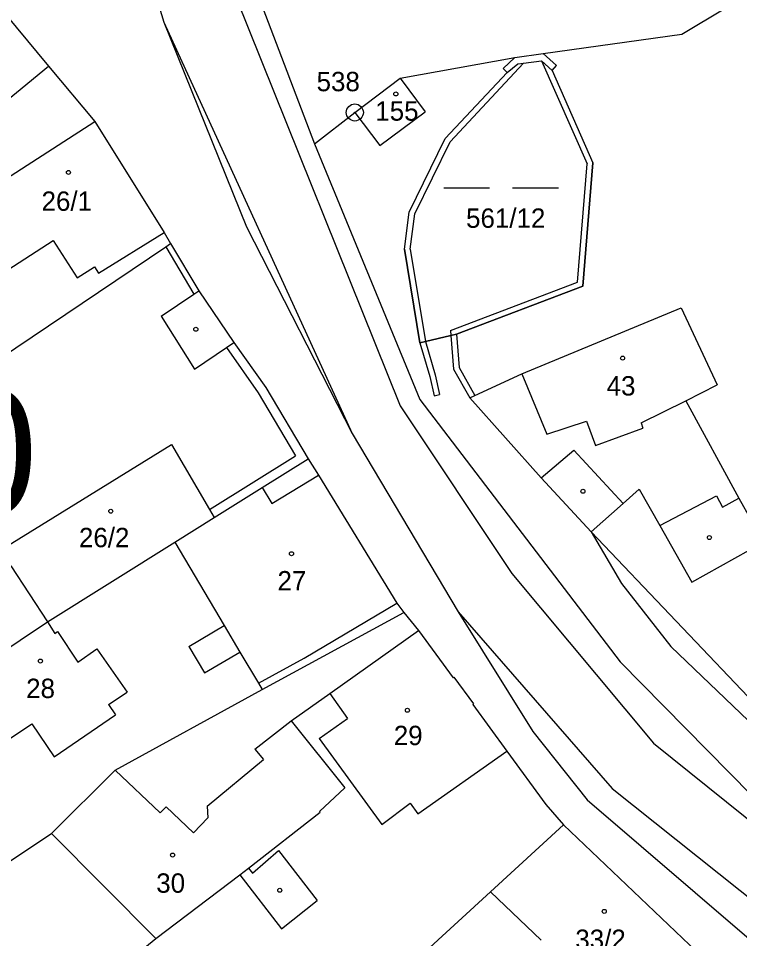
# Model space of a CAD drawing. Extents: x -725765 to -723182, y -1052705 to -1049154.
# Drawn here: x -724819.8 to -724756.6, y -1050950.1 to -1050869.4 of the extents above; entities that cross this region are included whole.
import ezdxf

# ---------------------------------------------------------------- set-up
doc = ezdxf.new("R2010")
doc.units = 0
for name, color, linetype in [('Vrstva 1', 7, 'Continuous'), ('Vrstva 17', 7, 'Continuous'), ('Vrstva 18', 7, 'Continuous'), ('Vrstva 19', 7, 'Continuous'), ('Vrstva 25', 7, 'Continuous'), ('Vrstva 4', 7, 'Continuous'), ('Vrstva 52', 7, 'Continuous'), ('Vrstva 53', 7, 'Continuous')]:
    doc.layers.add(name, color=color, linetype=linetype)

msp = doc.modelspace()

# ---------------------------------------------------------------- linework, layer by layer
at = {"layer": 'Vrstva 1'}
for points in [[(-724815.27, -1050842.75), (-724807.1, -1050869.67)], [(-724832.11, -1050855.56), (-724817.19, -1050873.53)], [(-724802.7, -1050857.13), (-724793.87, -1050880.36)], [(-724807.1, -1050869.67), (-724799.84, -1050887.62)], [(-724776.99, -1050874.1), (-724776.04, -1050873.34)], [(-724776.04, -1050873.34), (-724775.53, -1050873.27)], [(-724775.53, -1050873.27), (-724773.96, -1050873.06)], [(-724773.96, -1050873.06), (-724773.02, -1050873.91)], [(-724817.19, -1050873.53), (-724813.15, -1050878.39)], [(-724782.4, -1050879.89), (-724776.99, -1050874.1)], [(-724773.02, -1050873.91), (-724769.45, -1050882.02)], [(-724790.34, -1050877.6), (-724786.35, -1050874.6)], [(-724786.35, -1050874.6), (-724784.18, -1050877.55)], [(-724790.34, -1050877.6), (-724788.13, -1050880.5)], [(-724788.13, -1050880.5), (-724784.18, -1050877.55)], [(-724826.02, -1050886.69), (-724813.15, -1050878.39)], [(-724813.15, -1050878.39), (-724807.07, -1050888.13)], [(-724785.56, -1050886.34), (-724782.4, -1050879.89)], [(-724793.87, -1050880.36), (-724784.64, -1050902.78)], [(-724770.35, -1050892.84), (-724769.45, -1050882.02)], [(-724785.99, -1050889.59), (-724785.56, -1050886.34)], [(-724799.84, -1050887.62), (-724790.58, -1050905.75)], [(-724807.07, -1050888.13), (-724806.49, -1050889.1)], [(-724845.06, -1050915.06), (-724806.9, -1050889.38)], [(-724806.9, -1050889.38), (-724806.49, -1050889.1)], [(-724806.49, -1050889.1), (-724804.03, -1050893.25)], [(-724785.99, -1050889.59), (-724784.64, -1050897.81)], [(-724781.43, -1050897.06), (-724770.35, -1050892.84)], [(-724804.03, -1050893.25), (-724800.94, -1050897.77)], [(-724775.69, -1050900.52), (-724761.71, -1050894.73)], [(-724761.71, -1050894.73), (-724758.56, -1050901.48)], [(-724784.64, -1050897.81), (-724784.15, -1050897.7)], [(-724784.15, -1050897.7), (-724781.92, -1050897.18)], [(-724781.92, -1050897.18), (-724781.43, -1050897.06)], [(-724800.94, -1050897.77), (-724798.15, -1050901.74)], [(-724779.8, -1050902.43), (-724775.69, -1050900.52)], [(-724798.15, -1050901.74), (-724794.44, -1050907.99)], [(-724761.31, -1050902.89), (-724758.56, -1050901.48)], [(-724780.25, -1050902.64), (-724779.8, -1050902.43)], [(-724784.64, -1050902.78), (-724767.07, -1050925.79)], [(-724780.25, -1050902.64), (-724773.99, -1050909.66)], [(-724761.31, -1050902.89), (-724756.65, -1050911.44)], [(-724790.58, -1050905.75), (-724781.27, -1050921.4)], [(-724798.46, -1050910.5), (-724794.44, -1050907.99)], [(-724794.44, -1050907.99), (-724793.53, -1050909.41)], [(-724793.53, -1050909.41), (-724786.64, -1050920.65)], [(-724773.99, -1050909.66), (-724769.61, -1050914.39)], [(-724802.67, -1050913.13), (-724798.46, -1050910.5)], [(-724766.81, -1050911.91), (-724765.4, -1050910.66)], [(-724765.4, -1050910.66), (-724763.59, -1050913.84)], [(-724769.61, -1050914.39), (-724766.81, -1050911.91)], [(-724756.65, -1050911.44), (-724754.49, -1050915.3)], [(-724806.13, -1050915.3), (-724802.67, -1050913.13)], [(-724763.59, -1050913.84), (-724760.77, -1050918.8)], [(-724769.61, -1050914.39), (-724754.7, -1050930.05)], [(-724817.3, -1050922.28), (-724806.13, -1050915.3)], [(-724806.13, -1050915.3), (-724801.79, -1050922.61)], [(-724760.77, -1050918.8), (-724754.49, -1050915.3)], [(-724786.64, -1050920.65), (-724786.04, -1050921.45)], [(-724798.45, -1050928.23), (-724786.04, -1050921.45)], [(-724786.04, -1050921.45), (-724784.74, -1050923.04)], [(-724781.27, -1050921.4), (-724774.72, -1050931.91)], [(-724824.41, -1050927.04), (-724817.3, -1050922.28)], [(-724804.89, -1050924.45), (-724801.79, -1050922.61)], [(-724792.53, -1050928.57), (-724784.74, -1050923.04)], [(-724784.74, -1050923.04), (-724781.72, -1050927.21)], [(-724804.89, -1050924.45), (-724803.51, -1050926.77)], [(-724803.51, -1050926.77), (-724800.41, -1050924.93)], [(-724800.41, -1050924.93), (-724798.79, -1050927.66)], [(-724767.07, -1050925.79), (-724749.83, -1050943.31)], [(-724781.72, -1050927.21), (-724781.64, -1050927.15)], [(-724781.64, -1050927.15), (-724779.92, -1050929.48)], [(-724811.36, -1050935.29), (-724798.45, -1050928.23)], [(-724798.79, -1050927.66), (-724798.45, -1050928.23)], [(-724795.93, -1050930.98), (-724792.53, -1050928.57)], [(-724780, -1050929.54), (-724779.92, -1050929.48)], [(-724780, -1050929.54), (-724777.02, -1050933.62)], [(-724795.93, -1050930.98), (-724791.2, -1050936.85)], [(-724774.72, -1050931.91), (-724769.97, -1050937.91)], [(-724777.02, -1050933.62), (-724773.59, -1050938.3)], [(-724816.95, -1050940.84), (-724811.36, -1050935.29)], [(-724793.44, -1050938.91), (-724791.2, -1050936.85)], [(-724769.97, -1050937.91), (-724755.76, -1050950.09)], [(-724773.59, -1050938.3), (-724772.04, -1050940.08)], [(-724799.66, -1050943.89), (-724793.38, -1050938.99)], [(-724793.44, -1050938.91), (-724793.38, -1050938.99)], [(-724778.45, -1050945.98), (-724772.04, -1050940.08)], [(-724772.04, -1050940.08), (-724758.54, -1050952.96)], [(-724821.51, -1050943.86), (-724816.95, -1050940.84)], [(-724816.95, -1050940.84), (-724807.78, -1050950.05)], [(-724807.78, -1050950.05), (-724800.42, -1050944.47)], [(-724800.42, -1050944.47), (-724799.66, -1050943.89)], [(-724784.45, -1050951.5), (-724778.45, -1050945.98)], [(-724812.01, -1050953.52), (-724807.78, -1050950.05)]]:
    msp.add_lwpolyline(points, dxfattribs=at)
at = {"layer": 'Vrstva 25'}
for points in [[(-724782.535, -1050884.22), (-724778.515, -1050884.22)], [(-724776.504, -1050884.22), (-724772.484, -1050884.22)]]:
    msp.add_lwpolyline(points, dxfattribs=at)
for centre, radius in [((-724786.74, -1050875.98), 0.175), ((-724790.34, -1050877.6), 0.75), ((-724790.34, -1050877.6), 0.032), ((-724815.45, -1050882.86), 0.175), ((-724804.28, -1050896.62), 0.175), ((-724766.85, -1050899.15), 0.175), ((-724770.33, -1050910.83), 0.175), ((-724811.74, -1050912.58), 0.175), ((-724759.24, -1050914.89), 0.175), ((-724795.89, -1050916.31), 0.175), ((-724817.91, -1050925.72), 0.175), ((-724785.73, -1050930.04), 0.175), ((-724806.32, -1050942.74), 0.175), ((-724796.92, -1050945.83), 0.175), ((-724768.46, -1050947.68), 0.175)]:
    msp.add_circle(centre, radius, dxfattribs=at)
at = {"layer": 'Vrstva 4'}
for points in [[(-724761.65, -1050870.74), (-724750.38, -1050863.96)], [(-724800.77, -1050867.46), (-724786.35, -1050903.34)], [(-724807.1, -1050869.67), (-724790.58, -1050905.75)], [(-724773.82, -1050872.43), (-724761.65, -1050870.74)], [(-724776.31, -1050872.79), (-724773.82, -1050872.43)], [(-724773.82, -1050872.43), (-724772.64, -1050873.49)], [(-724786.35, -1050874.6), (-724776.31, -1050872.79)], [(-724781.98, -1050880.17), (-724775.53, -1050873.27)], [(-724777.32, -1050873.73), (-724776.31, -1050872.79)], [(-724773.96, -1050873.06), (-724769.96, -1050882.1)], [(-724773.02, -1050873.91), (-724772.64, -1050873.49)], [(-724826.16, -1050880.87), (-724817.19, -1050873.53)], [(-724777.32, -1050873.73), (-724776.99, -1050874.1)], [(-724793.87, -1050880.36), (-724790.34, -1050877.6)], [(-724785.07, -1050886.49), (-724781.98, -1050880.17)], [(-724770.82, -1050892.48), (-724769.96, -1050882.1)], [(-724785.48, -1050889.6), (-724785.07, -1050886.49)], [(-724812.82, -1050891.71), (-724807.07, -1050888.13)], [(-724822.3, -1050892.37), (-724816.8, -1050888.84)], [(-724816.8, -1050888.84), (-724814.7, -1050892.11)], [(-724806.9, -1050889.38), (-724804.45, -1050893.53)], [(-724785.48, -1050889.6), (-724784.15, -1050897.7)], [(-724814.7, -1050892.11), (-724813.18, -1050891.14)], [(-724813.18, -1050891.14), (-724812.82, -1050891.71)], [(-724781.96, -1050896.72), (-724770.82, -1050892.48)], [(-724807.33, -1050895.46), (-724804.45, -1050893.53)], [(-724804.45, -1050893.53), (-724804.03, -1050893.25)], [(-724807.33, -1050895.46), (-724804.39, -1050900.13)], [(-724781.96, -1050896.72), (-724781.92, -1050897.18)], [(-724784.15, -1050897.7), (-724783.28, -1050900.62)], [(-724781.92, -1050897.18), (-724781.68, -1050900.11)], [(-724781.43, -1050897.06), (-724781.19, -1050899.96)], [(-724804.39, -1050900.13), (-724801.6, -1050898.22)], [(-724801.6, -1050898.22), (-724800.94, -1050897.77)], [(-724801.6, -1050898.22), (-724798.81, -1050902.19)], [(-724784.64, -1050897.81), (-724783.76, -1050900.76)], [(-724781.68, -1050900.11), (-724780.25, -1050902.64)], [(-724781.19, -1050899.96), (-724779.8, -1050902.43)], [(-724783.76, -1050900.76), (-724783.39, -1050902.45)], [(-724783.28, -1050900.62), (-724782.9, -1050902.34)], [(-724775.69, -1050900.52), (-724773.49, -1050905.83)], [(-724798.81, -1050902.19), (-724795.53, -1050907.73)], [(-724783.39, -1050902.45), (-724782.9, -1050902.34)], [(-724786.35, -1050903.34), (-724776.58, -1050918.05)], [(-724765.23, -1050904.83), (-724761.31, -1050902.89)], [(-724773.49, -1050905.83), (-724770.01, -1050904.68)], [(-724770.01, -1050904.68), (-724769.22, -1050906.82)], [(-724765.23, -1050904.83), (-724765.09, -1050905.3)], [(-724769.22, -1050906.82), (-724765.09, -1050905.3)], [(-724821.4, -1050916), (-724806.41, -1050906.74)], [(-724806.41, -1050906.74), (-724803.07, -1050912.44)], [(-724773.99, -1050909.66), (-724771.12, -1050907.22)], [(-724771.12, -1050907.22), (-724766.81, -1050911.91)], [(-724803.07, -1050912.44), (-724795.53, -1050907.73)], [(-724797.61, -1050911.89), (-724793.53, -1050909.41)], [(-724798.46, -1050910.5), (-724797.61, -1050911.89)], [(-724763.59, -1050913.84), (-724758.63, -1050911.22)], [(-724758.63, -1050911.22), (-724758.09, -1050912.23)], [(-724758.09, -1050912.23), (-724756.65, -1050911.44)], [(-724803.07, -1050912.44), (-724802.67, -1050913.13)], [(-724769.61, -1050914.39), (-724766.96, -1050918.91)], [(-724820.51, -1050917.36), (-724817.3, -1050922.28)], [(-724776.58, -1050918.05), (-724764.15, -1050932.92)], [(-724766.96, -1050918.91), (-724762.62, -1050924.46)], [(-724794.79, -1050925.48), (-724786.64, -1050920.65)], [(-724781.27, -1050921.4), (-724767.77, -1050936.91)], [(-724817.3, -1050922.28), (-724816.64, -1050923.3)], [(-724801.79, -1050922.61), (-724800.41, -1050924.93)], [(-724816.64, -1050923.3), (-724816.4, -1050923.14)], [(-724816.4, -1050923.14), (-724814.62, -1050925.83)], [(-724814.62, -1050925.83), (-724812.95, -1050924.66)], [(-724812.95, -1050924.66), (-724810.29, -1050928.46)], [(-724762.62, -1050924.46), (-724755.82, -1050930.98)], [(-724798.79, -1050927.66), (-724794.79, -1050925.48)], [(-724811.95, -1050929.54), (-724810.29, -1050928.46)], [(-724792.53, -1050928.57), (-724790.97, -1050930.77)], [(-724811.95, -1050929.54), (-724811.33, -1050930.45)], [(-724816.69, -1050934.12), (-724811.33, -1050930.45)], [(-724793.46, -1050932.52), (-724790.97, -1050930.77)], [(-724822.44, -1050933.75), (-724818.66, -1050931.23)], [(-724818.66, -1050931.23), (-724816.69, -1050934.12)], [(-724799.11, -1050933.45), (-724795.93, -1050930.98)], [(-724793.46, -1050932.52), (-724787.96, -1050940.06)], [(-724764.15, -1050932.92), (-724737.04, -1050954.71)], [(-724799.11, -1050933.45), (-724798.35, -1050934.37)], [(-724784.82, -1050939.12), (-724777.02, -1050933.62)], [(-724803.28, -1050938.44), (-724798.35, -1050934.37)], [(-724811.36, -1050935.29), (-724807.41, -1050939.05)], [(-724767.77, -1050936.91), (-724739.7, -1050959.28)], [(-724807.41, -1050939.05), (-724806.88, -1050938.5)], [(-724806.88, -1050938.5), (-724804.47, -1050940.8)], [(-724803.28, -1050938.44), (-724803.22, -1050939.49)], [(-724787.96, -1050940.06), (-724785.47, -1050938.2)], [(-724785.47, -1050938.2), (-724784.82, -1050939.12)], [(-724804.47, -1050940.8), (-724803.22, -1050939.49)], [(-724799.31, -1050944.32), (-724797.03, -1050942.33)], [(-724797.03, -1050942.33), (-724793.64, -1050946.73)], [(-724800.42, -1050944.47), (-724796.78, -1050949.21)], [(-724799.66, -1050943.89), (-724799.31, -1050944.32)], [(-724778.45, -1050945.98), (-724774, -1050950.22)], [(-724796.78, -1050949.21), (-724793.64, -1050946.73)]]:
    msp.add_lwpolyline(points, dxfattribs=at)
at = {"layer": 'Vrstva 52'}
for points in [[(-724813.33, -1050644), (-724808.37, -1050650.73), (-724806.43, -1050654.63), (-724804.75, -1050661.51), (-724810.21, -1050691.79), (-724815, -1050731.09), (-724815.58, -1050758.85), (-724815.13, -1050787.45), (-724817.4, -1050803.09), (-724819.59, -1050825.69), (-724818.46, -1050833.53), (-724815.27, -1050842.75), (-724807.1, -1050869.67), (-724799.84, -1050887.62), (-724790.58, -1050905.75), (-724781.27, -1050921.4), (-724774.72, -1050931.91), (-724769.97, -1050937.91), (-724755.76, -1050950.09), (-724747.39, -1050955.27), (-724740.23, -1050960.06), (-724733.48, -1050964.31), (-724729, -1050967.94)], [(-724797.81, -1050648.79), (-724786.08, -1050660.92), (-724787.52, -1050665.42), (-724789.04, -1050670.2), (-724789.99, -1050673.16), (-724795.12, -1050673.64), (-724798.75, -1050677.64), (-724800.93, -1050691.71), (-724804.92, -1050728), (-724806.68, -1050763.03), (-724806.76, -1050807.12), (-724807.68, -1050827.87), (-724807.91, -1050834.06), (-724802.7, -1050857.13), (-724793.87, -1050880.36), (-724784.64, -1050902.78), (-724767.07, -1050925.79), (-724749.83, -1050943.31), (-724735.73, -1050952.08), (-724724.93, -1050961.09)], [(-724773.96, -1050873.06), (-724773.02, -1050873.91), (-724769.45, -1050882.02), (-724770.35, -1050892.84), (-724781.43, -1050897.06), (-724781.92, -1050897.18), (-724784.15, -1050897.7), (-724784.64, -1050897.81), (-724785.99, -1050889.59), (-724785.56, -1050886.34), (-724782.4, -1050879.89), (-724776.99, -1050874.1), (-724776.04, -1050873.34), (-724775.53, -1050873.27), (-724773.96, -1050873.06)]]:
    msp.add_lwpolyline(points, dxfattribs=at)

# ---------------------------------------------------------------- texts
at = {"layer": 'Vrstva 17'}
msp.add_text('538', height=1.7, dxfattribs=at).set_placement((-724793.69, -1050875.74))
at = {"layer": 'Vrstva 18'}
msp.add_text('561/12', height=1.7, dxfattribs=at).set_placement((-724780.58, -1050887.72))
at = {"layer": 'Vrstva 19'}
for s, p in [('155', (-724788.54, -1050878.32)), ('26/1', (-724817.81, -1050886.23)), ('43', (-724768.25, -1050902.43)), ('26/2', (-724814.53, -1050915.74)), ('27', (-724797.12, -1050919.53)), ('28', (-724819.16, -1050928.97)), ('29', (-724786.92, -1050933.1)), ('30', (-724807.75, -1050946.05)), ('33/2', (-724771, -1050950.98))]:
    msp.add_text(s, height=1.7, dxfattribs=at).set_placement(p)
at = {"layer": 'Vrstva 53'}
msp.add_text('21010', height=11, dxfattribs=at).set_placement((-724859.06, -1050912.906))

doc.saveas('drawing.dxf')
